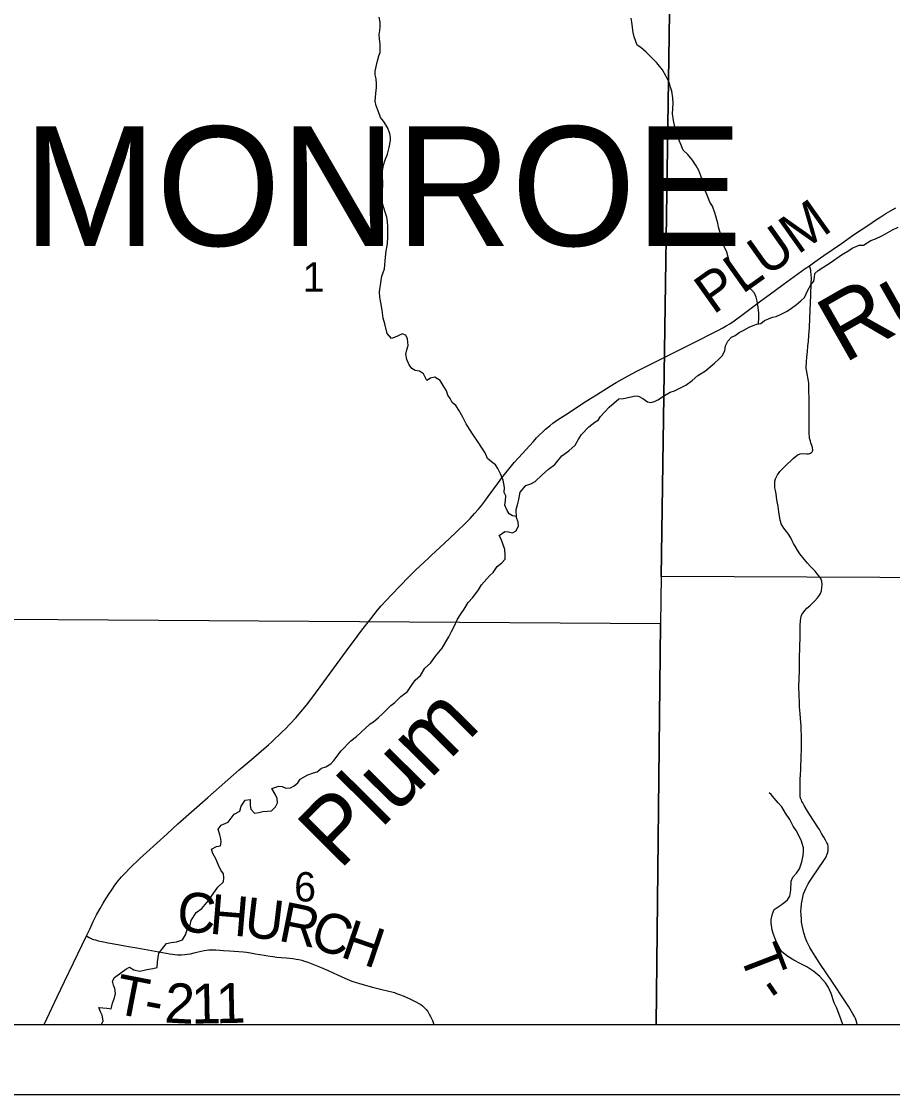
# Model space of a CAD drawing. Extents: x -7.1 to 34, y 0 to 22.
# Drawn here: x 2.879 to 4.122, y 14 to 15.53 of the extents above; entities that cross this region are included whole.
import ezdxf

# ---------------------------------------------------------------- set-up
doc = ezdxf.new("R2010")
doc.units = 0
for name, color, linetype in [('GM_X_County_Road', 7, 'Continuous'), ('GM_X_County_Road_Text', 7, 'Continuous'), ('GM_X_Minor_River', 7, 'Continuous'), ('GM_X_Minor_River_Text', 7, 'Continuous'), ('GM_X_Section', 7, 'Continuous'), ('GM_X_Section_Text', 7, 'Continuous'), ('GM_X_Township_Road', 7, 'Continuous'), ('GM_X_Township_Road_Text', 7, 'Continuous'), ('GM_X_Township_Text', 7, 'Continuous'), ('GM_X_Unincorporated', 7, 'Continuous'), ('SH_Cut_Line', 7, 'Continuous'), ('SH_Data', 7, 'Continuous')]:
    doc.layers.add(name, color=color, linetype=linetype)

msp = doc.modelspace()

# ---------------------------------------------------------------- linework, layer by layer
at = {"layer": 'GM_X_County_Road'}
for points in [[(2.9719, 14.2261), (2.9771, 14.2369), (2.9818, 14.2467), (2.9865, 14.2562), (2.9915, 14.2654), (2.9957, 14.2727), (2.9995, 14.2793), (3.0039, 14.2858), (3.0081, 14.292), (3.0127, 14.2988), (3.0173, 14.3049), (3.0218, 14.3103), (3.0271, 14.3157), (3.0336, 14.3225), (3.048, 14.3364), (3.0575, 14.3452), (3.087, 14.3718), (3.1026, 14.3861), (3.1454, 14.4237), (3.1901, 14.4632), (3.2043, 14.4751), (3.2318, 14.4986), (3.236, 14.5026), (3.2517, 14.5175), (3.2559, 14.5217), (3.2623, 14.5282), (3.2711, 14.5378), (3.2756, 14.5428), (3.2858, 14.5554), (3.2919, 14.5633), (3.3054, 14.5815), (3.343, 14.6328), (3.3581, 14.6532), (3.3649, 14.6623), (3.3775, 14.6783), (3.3823, 14.6847), (3.3872, 14.6908), (3.3924, 14.6968), (3.3995, 14.7043), (3.407, 14.7124), (3.4317, 14.7381), (3.4415, 14.7479), (3.4606, 14.7656), (3.4644, 14.7691), (3.4825, 14.786), (3.4991, 14.8016), (3.5137, 14.8159), (3.5193, 14.8216), (3.5256, 14.8284), (3.5313, 14.8349), (3.5358, 14.8405), (3.5401, 14.8461), (3.5451, 14.8529), (3.5519, 14.8621), (3.5598, 14.8729), (3.5648, 14.8795), (3.5821, 14.9011), (3.5882, 14.9081), (3.6095, 14.9315), (3.6142, 14.9366), (3.6183, 14.941), (3.6224, 14.9448), (3.6267, 14.9488), (3.6328, 14.9538), (3.6373, 14.9573), (3.6442, 14.962), (3.6552, 14.9694), (3.6849, 14.9887), (3.6994, 14.9979), (3.7191, 15.0104), (3.7276, 15.0154), (3.7448, 15.0249), (3.7573, 15.0315), (3.7992, 15.0526), (3.835, 15.0705), (3.8736, 15.09), (3.8799, 15.0934), (3.8846, 15.0961), (3.8898, 15.0993), (3.8958, 15.1034), (3.9069, 15.1113), (3.9219, 15.1229), (3.9338, 15.1318), (3.9459, 15.1405), (3.9659, 15.1553), (3.9974, 15.1778), (4.0035, 15.182), (4.0112, 15.1875), (4.0237, 15.1963), (4.049, 15.2136), (4.0664, 15.2258), (4.088, 15.2402), (4.0978, 15.2467), (4.1051, 15.2517), (4.1121, 15.2562), (4.119, 15.2602), (4.1265, 15.2643)], [(2.9116, 14.1), (2.9303, 14.1393), (2.9406, 14.1614), (2.9535, 14.1878), (2.9719, 14.2261)]]:
    msp.add_lwpolyline(points, dxfattribs=at)
at = {"layer": 'GM_X_Minor_River'}
for points in [[(3.3897, 15.5119), (3.3904, 15.5172), (3.3911, 15.5222), (3.391, 15.5291), (3.3897, 15.5363)], [(3.9306, 15.0989), (3.931, 15.108), (3.9313, 15.1141), (3.93, 15.1224), (3.9288, 15.1316), (3.9275, 15.1369), (3.9252, 15.1429), (3.9175, 15.1512), (3.9094, 15.1579), (3.8999, 15.1646), (3.8956, 15.171), (3.8921, 15.1801), (3.8893, 15.1869), (3.8853, 15.2013), (3.8818, 15.2093), (3.8794, 15.2199), (3.877, 15.2255), (3.8754, 15.2308), (3.8738, 15.2369), (3.8726, 15.2426), (3.8714, 15.2475), (3.8698, 15.2525), (3.8686, 15.2574), (3.8651, 15.2668), (3.8612, 15.2725), (3.8573, 15.2827), (3.8545, 15.2891), (3.8517, 15.3013), (3.8482, 15.31), (3.8454, 15.3179), (3.8419, 15.3243), (3.8365, 15.3323), (3.8299, 15.3405), (3.8234, 15.3469), (3.8203, 15.3537), (3.8179, 15.3594), (3.8147, 15.3688), (3.8115, 15.3798), (3.8095, 15.3889), (3.8082, 15.3984), (3.8088, 15.4133), (3.8083, 15.4213), (3.807, 15.4308), (3.805, 15.4368), (3.8038, 15.4421), (3.7991, 15.4516), (3.7937, 15.4614), (3.7856, 15.4712), (3.7779, 15.4787), (3.7706, 15.4865), (3.7629, 15.4933), (3.7576, 15.4966), (3.7533, 15.5083), (3.752, 15.5144), (3.7499, 15.5292), (3.7491, 15.5349)], [(3.5856, 14.8245), (3.58, 14.8252), (3.575, 14.8281), (3.5723, 14.833), (3.5688, 14.8406), (3.5698, 14.8471), (3.5701, 14.8536), (3.5678, 14.8585), (3.5684, 14.8657), (3.5664, 14.8763), (3.5628, 14.8854), (3.5589, 14.8926), (3.5554, 14.8982), (3.5497, 14.9023), (3.5443, 14.9068), (3.5408, 14.9151), (3.5358, 14.9223), (3.5307, 14.9302), (3.5238, 14.9408), (3.5184, 14.9487), (3.5137, 14.9566), (3.509, 14.966), (3.5032, 14.9758), (3.4989, 14.9826), (3.4939, 14.9871), (3.4908, 14.9924), (3.4877, 14.9973), (3.4857, 15.0034), (3.4811, 15.0113), (3.4768, 15.0181), (3.4692, 15.0229), (3.4628, 15.0217), (3.4575, 15.0181), (3.4528, 15.028), (3.4471, 15.0317), (3.441, 15.0327), (3.4361, 15.0353), (3.4326, 15.0406), (3.4291, 15.0482), (3.4278, 15.0558), (3.4292, 15.0622), (3.431, 15.068), (3.4301, 15.0779), (3.4274, 15.0828), (3.4225, 15.0846), (3.4149, 15.0811), (3.407, 15.0783), (3.4009, 15.0854), (3.3976, 15.0991), (3.3953, 15.107), (3.394, 15.1184), (3.3919, 15.1294), (3.3907, 15.137), (3.3902, 15.1446), (3.3926, 15.161), (3.3936, 15.1671), (3.3973, 15.1775), (3.3979, 15.1828), (3.3982, 15.1893), (3.3995, 15.203), (3.4013, 15.2133), (3.4019, 15.2232), (3.4021, 15.2327), (3.402, 15.2381), (3.4016, 15.2445), (3.4003, 15.251), (3.3983, 15.2582), (3.3944, 15.2707), (3.392, 15.2756), (3.3923, 15.2824), (3.3945, 15.2897), (3.3948, 15.2969), (3.3945, 15.3125), (3.3945, 15.3175), (3.3959, 15.3255), (3.398, 15.3331), (3.4017, 15.3412), (3.4038, 15.3507), (3.4056, 15.3603), (3.4059, 15.3652), (3.4047, 15.3705), (3.4015, 15.3793), (3.3957, 15.3883), (3.3915, 15.3932), (3.3887, 15.4015), (3.3852, 15.4098), (3.3839, 15.4167), (3.3849, 15.4277), (3.3859, 15.4361), (3.3858, 15.4414), (3.3853, 15.4487), (3.3841, 15.4543), (3.3837, 15.4593), (3.3858, 15.4681), (3.3872, 15.4742), (3.389, 15.4811), (3.3909, 15.486), (3.3912, 15.491), (3.3911, 15.4986), (3.3902, 15.5051), (3.3897, 15.5119)], [(3.6503, 14.9107), (3.66, 14.9181), (3.669, 14.9259), (3.6734, 14.9335), (3.6782, 14.9412), (3.6887, 14.952), (3.6973, 14.959), (3.7022, 14.9618), (3.7055, 14.9668), (3.7178, 14.9803), (3.7313, 14.9919), (3.7381, 14.9924), (3.749, 14.9952), (3.7547, 14.9964), (3.7596, 14.9961), (3.7657, 14.9924), (3.7722, 14.988), (3.7772, 14.9869), (3.7824, 14.9885), (3.7873, 14.9905), (3.7967, 14.9971), (3.8046, 15.0014), (3.811, 15.0034), (3.8166, 15.0062), (3.8271, 15.0116), (3.8361, 15.0182), (3.844, 15.0256), (3.8552, 15.0322), (3.8624, 15.0381), (3.868, 15.0431), (3.8743, 15.0485), (3.8788, 15.0535), (3.8828, 15.0608), (3.8835, 15.0677), (3.8868, 15.0742), (3.892, 15.08), (3.8973, 15.0824), (3.9029, 15.0866), (3.9086, 15.0894), (3.9176, 15.0945), (3.9232, 15.0968), (3.9285, 15.0984), (3.9338, 15.0997), (3.9394, 15.1036), (3.9507, 15.1087), (3.956, 15.1095), (3.9631, 15.1131), (3.9718, 15.117), (3.9778, 15.1213), (3.9849, 15.1267), (3.9912, 15.1318), (3.9965, 15.1368), (4.0012, 15.1471), (4.0053, 15.1548), (4.0098, 15.1598), (4.0104, 15.1652), (4.0111, 15.1709), (4.016, 15.1751), (4.0343, 15.1868), (4.049, 15.1973), (4.058, 15.2028), (4.0643, 15.2071), (4.0745, 15.2111), (4.0806, 15.2115), (4.0907, 15.2178), (4.0975, 15.2202), (4.1065, 15.2245), (4.1118, 15.2272), (4.1219, 15.2331), (4.1298, 15.237)], [(3.1605, 14.327), (3.1566, 14.336), (3.1524, 14.3436), (3.1504, 14.35), (3.1575, 14.3536), (3.1632, 14.3548), (3.1642, 14.3598), (3.1638, 14.3647), (3.1622, 14.3704), (3.1598, 14.3783), (3.1643, 14.3841), (3.174, 14.3884), (3.1826, 14.4), (3.1908, 14.4043), (3.1926, 14.4112), (3.1982, 14.4196), (3.2054, 14.4209), (3.2055, 14.4121), (3.2063, 14.4068), (3.2117, 14.4012), (3.2181, 14.4024), (3.2238, 14.4037), (3.2302, 14.4042), (3.2359, 14.4046), (3.2415, 14.4104), (3.2444, 14.4162), (3.244, 14.4223), (3.2412, 14.4283), (3.2366, 14.4366), (3.2464, 14.4398), (3.2513, 14.4395), (3.2566, 14.4369), (3.2631, 14.4374), (3.2683, 14.4401), (3.2736, 14.4444), (3.2769, 14.4498), (3.2878, 14.4557), (3.2957, 14.4588), (3.301, 14.4604), (3.3073, 14.4655), (3.3137, 14.4675), (3.3205, 14.4714), (3.325, 14.4764), (3.3354, 14.4903), (3.3492, 14.5042), (3.3574, 14.5108), (3.3641, 14.5166), (3.3768, 14.5286), (3.3817, 14.5317), (3.3884, 14.5375), (3.3944, 14.5429), (3.4064, 14.5549), (3.412, 14.5592), (3.4206, 14.5677), (3.4299, 14.5747), (3.4347, 14.582), (3.4407, 14.5908), (3.4485, 14.5974), (3.4548, 14.6082), (3.463, 14.6152), (3.4701, 14.6252), (3.4794, 14.6367), (3.4845, 14.6456), (3.489, 14.6525), (3.4927, 14.6602), (3.496, 14.6667), (3.5011, 14.6778), (3.5067, 14.6859), (3.5107, 14.6924), (3.5167, 14.7016), (3.523, 14.7086), (3.5312, 14.7197), (3.5356, 14.7267), (3.5472, 14.7398), (3.552, 14.7444), (3.5579, 14.7529), (3.5647, 14.7583), (3.5695, 14.7633), (3.5694, 14.769), (3.5689, 14.7774), (3.5662, 14.7854), (3.5634, 14.7918), (3.5607, 14.7971), (3.5689, 14.8029), (3.5743, 14.8026), (3.58, 14.8012), (3.5848, 14.8039), (3.5885, 14.8108), (3.5881, 14.8161), (3.5857, 14.823), (3.5851, 14.8344), (3.5869, 14.8412), (3.5887, 14.8485), (3.5908, 14.8588), (3.5987, 14.8685), (3.6058, 14.8708), (3.6122, 14.8744), (3.6219, 14.8837), (3.6313, 14.8918), (3.6402, 14.8984), (3.6503, 14.9107)], [(4.051, 14.1), (4.0486, 14.1065), (4.0423, 14.1232), (4.0388, 14.1307), (4.0344, 14.144), (4.0305, 14.1527), (4.0263, 14.1595), (4.0182, 14.1685), (4.0097, 14.1756), (3.9998, 14.1819), (3.9903, 14.1871), (3.9811, 14.1915), (3.9723, 14.1967), (3.9639, 14.2034), (3.9604, 14.2098), (3.9553, 14.2197), (3.9518, 14.2295), (3.9502, 14.2348), (3.9489, 14.2443), (3.9488, 14.2496), (3.9506, 14.2576), (3.9532, 14.2638), (3.9644, 14.2716), (3.9719, 14.2778), (3.9752, 14.2831), (3.9766, 14.2915), (3.9772, 14.3041), (3.9798, 14.3099), (3.985, 14.3156), (3.9891, 14.3218), (3.9923, 14.3317), (3.9945, 14.3409), (3.9948, 14.3459), (3.9947, 14.3516), (3.9915, 14.3629), (3.9845, 14.3765), (3.9802, 14.3829), (3.9752, 14.3924), (3.9693, 14.4014), (3.9639, 14.4105), (3.9589, 14.4161), (3.9531, 14.4225), (3.9489, 14.4278), (3.9457, 14.4303)], [(2.9936, 14.1), (2.9957, 14.1052), (2.9944, 14.1132), (2.9921, 14.1181), (2.9897, 14.1241), (3.0011, 14.1232), (3.0072, 14.1221), (3.0093, 14.1305), (3.0122, 14.1378), (3.0137, 14.1439), (3.0124, 14.1511), (3.0108, 14.1561), (3.0092, 14.1617), (3.0122, 14.1667), (3.0283, 14.1788), (3.0336, 14.1815), (3.0397, 14.1778), (3.0477, 14.176), (3.0526, 14.1769), (3.0582, 14.1781), (3.0669, 14.1797), (3.073, 14.181), (3.0736, 14.1894), (3.0753, 14.2016), (3.0861, 14.2154), (3.0929, 14.2167), (3.1004, 14.2179), (3.1091, 14.2207), (3.1135, 14.2277), (3.1164, 14.2361), (3.1202, 14.2415), (3.1216, 14.248), (3.1286, 14.2595), (3.1365, 14.2653), (3.1461, 14.2769), (3.1506, 14.283), (3.1595, 14.2957), (3.1673, 14.3035), (3.168, 14.3088), (3.1675, 14.3149), (3.1637, 14.3202), (3.1605, 14.327)]]:
    msp.add_lwpolyline(points, dxfattribs=at)
at = {"layer": 'GM_X_Section'}
for points in [[(4.645, 15.7523), (4.6234, 14.7351), (3.7918, 14.7389), (3.8055, 15.6719), (3.8073, 15.7595)], [(2.8016, 15.6921), (3.8055, 15.6719), (3.7918, 14.7389), (3.7909, 14.6711), (2.7883, 14.6781)]]:
    msp.add_lwpolyline(points, close=True, dxfattribs=at)
at = {"layer": 'GM_X_Township_Road'}
for points in [[(2.1, 17.7253), (2.1, 14.1), (6.633, 14.1), (6.6565, 15.1357), (6.6586, 15.2372), (6.6748, 15.9993), (6.6822, 16.3488), (6.7058, 17.2839), (6.7118, 17.7486)], [(4.0029, 14.962), (4.003, 14.9886), (4.0027, 15.0079), (4.0023, 15.0143), (4.0017, 15.02), (4.0002, 15.0279), (3.9995, 15.0309), (3.9989, 15.0356), (3.9988, 15.0374), (3.999, 15.0443), (3.9995, 15.052), (4.0004, 15.0593), (4.0013, 15.0676), (4.0018, 15.0739), (4.0026, 15.0831), (4.0033, 15.0933), (4.004, 15.1073), (4.0052, 15.1398), (4.0059, 15.1573), (4.0061, 15.1641), (4.0055, 15.1738), (4.0052, 15.1755), (4.0045, 15.1788), (4.0035, 15.182)], [(3.9927, 14.418), (3.9918, 14.4199), (3.9908, 14.4228), (3.9903, 14.4249), (3.99, 14.4272), (3.9899, 14.4296), (3.99, 14.444), (3.9902, 14.4498), (3.9905, 14.4557), (3.9909, 14.4635), (3.9912, 14.47), (3.9915, 14.4772), (3.9917, 14.4843), (3.9919, 14.4903), (3.9921, 14.5068), (3.9914, 14.526), (3.9911, 14.5312), (3.9907, 14.5364), (3.9901, 14.5434), (3.9897, 14.5483), (3.9894, 14.5529), (3.9892, 14.5589), (3.9887, 14.5696), (3.9884, 14.5813), (3.989, 14.6049), (3.9893, 14.6226), (3.9899, 14.6525), (3.99, 14.6686), (3.9906, 14.6762), (3.991, 14.6791), (3.9916, 14.6816), (3.9925, 14.6844), (3.9938, 14.6866), (3.9973, 14.6909), (3.9998, 14.6934), (4.0037, 14.6969), (4.0109, 14.7041), (4.0148, 14.7085), (4.0175, 14.7123), (4.0191, 14.7146), (4.0204, 14.7183), (4.0211, 14.7232), (4.0213, 14.7269), (4.021, 14.7321), (4.0201, 14.7345), (4.0194, 14.7361), (4.0168, 14.7395), (4.0146, 14.7425), (4.0113, 14.7464), (4.0084, 14.7497), (4.0043, 14.7536), (4.0008, 14.7577), (3.9957, 14.7637), (3.9897, 14.7713), (3.9864, 14.7761), (3.983, 14.7818), (3.9807, 14.7859), (3.9788, 14.7898), (3.9766, 14.7937), (3.9734, 14.799), (3.9704, 14.8029), (3.9666, 14.8077), (3.9643, 14.8114), (3.9631, 14.814), (3.9624, 14.8162), (3.9615, 14.8193), (3.9598, 14.8311), (3.9586, 14.8384), (3.9569, 14.8481), (3.9557, 14.8565), (3.9548, 14.8613), (3.9542, 14.8654), (3.9538, 14.8704), (3.9541, 14.8746), (3.955, 14.878), (3.9563, 14.881), (3.9579, 14.8839), (3.9602, 14.887), (3.9611, 14.8883), (3.9655, 14.893), (3.9688, 14.8962), (3.9719, 14.8992), (3.9766, 14.9039), (3.9802, 14.9072), (3.9829, 14.9094), (3.9856, 14.9114), (3.9875, 14.9127), (3.989, 14.9134), (3.99, 14.9138), (3.9928, 14.9142), (3.9998, 14.9139), (4.0019, 14.9138), (4.0038, 14.9141), (4.005, 14.9145), (4.0065, 14.9155), (4.0073, 14.9164), (4.0078, 14.9175), (4.0082, 14.9187), (4.0079, 14.9226), (4.0074, 14.9243), (4.0055, 14.9294), (4.0047, 14.9317), (4.0036, 14.9362), (4.0033, 14.9379), (4.0028, 14.9428), (4.0028, 14.947), (4.0029, 14.961), (4.0029, 14.962)], [(4.0713, 14.1), (4.0709, 14.1021), (4.0699, 14.1054), (4.0689, 14.1083), (4.0675, 14.1114), (4.0654, 14.1152), (4.0597, 14.125), (4.0528, 14.1351), (4.037, 14.1589), (4.0182, 14.1869), (4.0114, 14.1971), (4.0067, 14.2047), (4.0039, 14.2095), (4.0015, 14.2143), (3.9998, 14.2183), (3.9979, 14.2231), (3.9955, 14.2306), (3.9939, 14.2366), (3.9929, 14.241), (3.9922, 14.2458), (3.9918, 14.2502), (3.9914, 14.2561), (3.9913, 14.2622), (3.9914, 14.2648), (3.9921, 14.272), (3.9925, 14.2745), (3.9934, 14.279), (3.9945, 14.2838), (3.9951, 14.286), (3.9968, 14.2907), (3.9982, 14.2937), (4.0017, 14.3005), (4.0039, 14.3042), (4.0075, 14.3098), (4.0238, 14.3339), (4.0256, 14.3366), (4.0275, 14.34), (4.0284, 14.342), (4.0294, 14.345), (4.0302, 14.3485), (4.0303, 14.351), (4.03, 14.3544), (4.0294, 14.3569), (4.0284, 14.3591), (4.0265, 14.3626), (4.0239, 14.3671), (4.0207, 14.3723), (4.0176, 14.3778), (4.0155, 14.3811), (4.0038, 14.3987), (3.999, 14.4063), (3.9957, 14.412), (3.9937, 14.416), (3.9927, 14.418)], [(2.9719, 14.2261), (2.976, 14.2238), (2.9787, 14.2225), (2.9805, 14.2218), (2.9821, 14.2211), (2.9847, 14.2204), (2.9887, 14.2193), (2.9942, 14.2181), (3.0032, 14.2163), (3.0168, 14.2139), (3.0322, 14.2113), (3.0437, 14.2094), (3.0911, 14.2007), (3.095, 14.2), (3.0982, 14.1995), (3.1018, 14.1992), (3.1051, 14.1991), (3.1078, 14.1992), (3.1122, 14.1996), (3.1162, 14.2001), (3.1203, 14.2008), (3.1256, 14.202), (3.1313, 14.2034), (3.1401, 14.2054), (3.1435, 14.2059), (3.1467, 14.2063), (3.1508, 14.2064), (3.1567, 14.2062), (3.1624, 14.2058), (3.1676, 14.2054), (3.1759, 14.2048), (3.1826, 14.2045), (3.1896, 14.2039), (3.196, 14.2033), (3.2005, 14.2029), (3.2061, 14.202), (3.2132, 14.2007), (3.2195, 14.1996), (3.2255, 14.1986), (3.2309, 14.1978), (3.2379, 14.1968), (3.2437, 14.1961), (3.2497, 14.1955), (3.2569, 14.1948), (3.2666, 14.1938), (3.2711, 14.1932), (3.2752, 14.1925), (3.2792, 14.1915), (3.2833, 14.1904), (3.2876, 14.189), (3.2926, 14.1871), (3.2973, 14.1852), (3.3069, 14.1812), (3.318, 14.1762), (3.33, 14.1706), (3.3407, 14.1658), (3.3439, 14.1645), (3.3504, 14.1619), (3.3567, 14.1597), (3.3599, 14.1587), (3.3683, 14.1563), (3.375, 14.1546), (3.3801, 14.1533), (3.3914, 14.1505), (3.4034, 14.1476), (3.4075, 14.1464), (3.4113, 14.1454), (3.4145, 14.1443), (3.4188, 14.1428), (3.4237, 14.1409), (3.4331, 14.1367), (3.443, 14.1319), (3.4464, 14.13), (3.4491, 14.1283), (3.4516, 14.1263), (3.4544, 14.1237), (3.4565, 14.1213), (3.4588, 14.1183), (3.4611, 14.1147), (3.463, 14.1111), (3.4655, 14.1056), (3.4676, 14.1)]]:
    msp.add_lwpolyline(points, dxfattribs=at)
at = {"layer": 'GM_X_Unincorporated'}
for points in [[(3.7847, 14.1), (4.6065, 14.1), (4.6234, 14.7351), (3.7918, 14.7389), (3.7909, 14.6711)], [(2.7742, 14.1), (3.7847, 14.1), (3.7909, 14.6711), (2.7883, 14.6781)]]:
    msp.add_lwpolyline(points, close=True, dxfattribs=at)
at = {"layer": 'SH_Cut_Line'}
msp.add_lwpolyline([(2.1, 17.7253), (2.1, 14.1), (8.9, 14.1), (8.9, 17.7079), (8.6668, 17.7136), (8.4472, 17.7189), (7.7202, 17.7285), (6.7118, 17.7486), (6.3575, 17.7557), (6.1904, 17.7592), (5.7514, 17.7685), (5.5047, 17.7737), (5.1115, 17.7819), (5.0544, 17.7831), (5.0443, 17.7832), (4.7094, 17.7848), (4.5657, 17.7857), (4.3, 17.7873), (3.8304, 17.7952), (3.8238, 17.6717), (3.7215, 17.6707), (3.0659, 17.6986), (2.7886, 17.7105), (2.5551, 17.7155)], close=True, dxfattribs=at)
at = {"layer": 'SH_Data'}
for p, q in [((2.1, 14.1), (8.9, 14.1)), ((2, 14), (9, 14))]:
    msp.add_line(p, q, dxfattribs=at)

# ---------------------------------------------------------------- texts
at = {"layer": 'GM_X_County_Road_Text'}
msp.add_text('PLUM', height=0.05682, rotation=35.375, dxfattribs=at).set_placement((3.8662, 15.1114))
at = {"layer": 'GM_X_Minor_River_Text'}
for s, rotation, p in [('Run', 29.6968, (4.0528, 15.0419)), ('Plum', 45.2251, (3.3333, 14.3188))]:
    msp.add_text(s, height=0.09469, rotation=rotation, dxfattribs=at).set_placement(p)
at = {"layer": 'GM_X_Section_Text'}
for s, p in [('1', (3.2804, 15.1449)), ('6', (3.2683, 14.2753))]:
    msp.add_text(s, height=0.0419, rotation=0, dxfattribs=at).set_placement(p)
at = {"layer": 'GM_X_Township_Road_Text'}
for s, rotation, p in [('C', 355.7028, (3.0999, 14.233)), ('H', 355.2554, (3.1463, 14.2295)), ('U', 353.2491, (3.1956, 14.2254)), ('R', 348.5867, (3.2441, 14.2197)), ('C', 342.3587, (3.2882, 14.2109)), ('H', 341.2229, (3.3324, 14.1969)), ('T', 291.0461, (3.9026, 14.2009)), ('T', 349.0263, (3.0095, 14.1164)), ('2', 356.8975, (3.0826, 14.1029)), ('1', 1.0514, (3.122, 14.101)), ('1', 1.2599, (3.1572, 14.1016)), ('-', 304.6693, (3.9247, 14.1483)), ('-', 349.385, (3.0516, 14.1082))]:
    msp.add_text(s, height=0.0568, rotation=rotation, dxfattribs=at).set_placement(p)
at = {"layer": 'GM_X_Township_Text'}
msp.add_text('MONROE', height=0.17045, rotation=0, dxfattribs=at).set_placement((2.8818, 15.2103))

doc.saveas('drawing.dxf')
